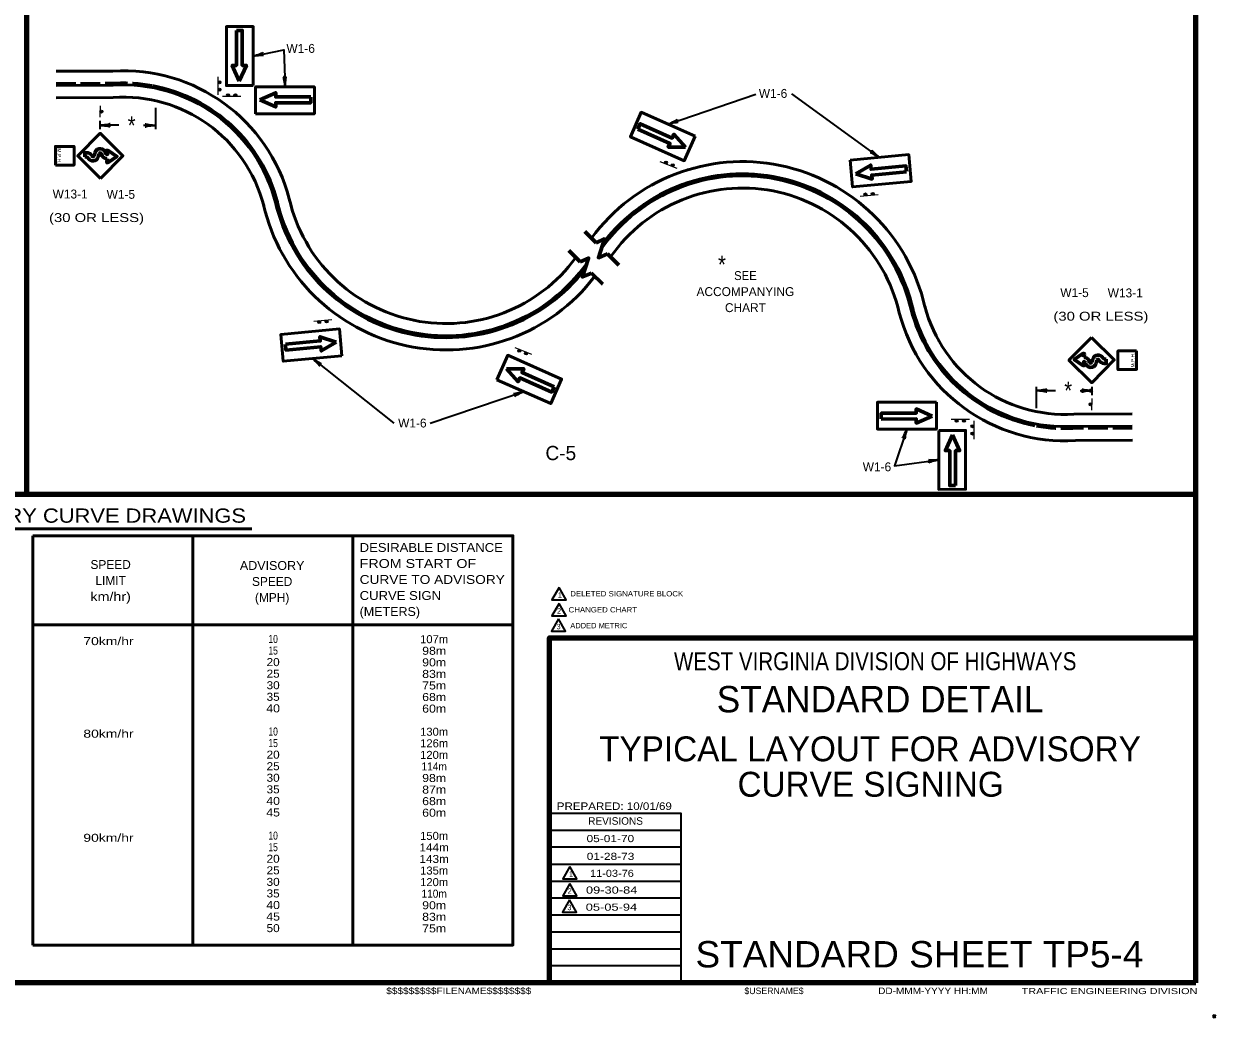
# Model space of a CAD drawing. Extents: x 522 to 1378, y -343 to 201.
# Drawn here: x 975.7 to 1377.6, y -343.4 to -8.5 of the extents above; entities that cross this region are included whole.
import ezdxf
from ezdxf.enums import TextEntityAlignment as Align

# ---------------------------------------------------------------- set-up
doc = ezdxf.new("R2010")
doc.units = 0
doc.header["$LTSCALE"] = 1.1
doc.header["$PDMODE"] = 32
doc.header["$PDSIZE"] = 0.55
doc.linetypes.add('LONG_DASHED', pattern=[7.5, 6, -1.5])
for name, color, linetype, lineweight in [('1', 7, 'Continuous', 53), ('4', 7, 'Continuous', 25), ('61', 7, 'Continuous', 35)]:
    doc.layers.add(name, color=color, linetype=linetype, lineweight=lineweight)

msp = doc.modelspace()

# ---------------------------------------------------------------- hatches: boundary and pattern name
at = {"layer": '4'}
for points in [[(1041.737, -28.71, 1), (1041.739, -27.726, 1)], [(1041.734, -31.178, 1), (1041.737, -30.194, 1)], [(1045.105, -32.546, 1), (1044.121, -32.543, 1)], [(1047.573, -32.548, 1), (1046.589, -32.546, 1)], [(1001.899, -38.586, 1), (1001.907, -37.602, 1)], [(1192.771, -55.429, 1), (1191.86, -55.058, 1)], [(1195.058, -56.357, 1), (1194.147, -55.986, 1)], [(1260.07, -65.984, 1), (1259.089, -66.059, 1)], [(1262.531, -65.79, 1), (1261.55, -65.866, 1)], [(1077.357, -108.892, 1), (1078.338, -108.817, 1)], [(1074.896, -109.086, 1), (1075.877, -109.01, 1)], [(1142.369, -118.519, 1), (1143.28, -118.89, 1)], [(1144.656, -119.447, 1), (1145.567, -119.818, 1)], [(1335.528, -136.29, 1), (1335.52, -137.274, 1)], [(1289.854, -142.328, 1), (1290.838, -142.33, 1)], [(1292.322, -142.33, 1), (1293.306, -142.333, 1)], [(1295.693, -143.698, 1), (1295.69, -144.682, 1)], [(1295.69, -146.166, 1), (1295.688, -147.15, 1)]]:
    msp.add_hatch(color=256, dxfattribs=at).paths.add_polyline_path(points)

# ---------------------------------------------------------------- linework, layer by layer
at = {"layer": '1', "lineweight": 158}
for q in [(1370.988, 194.26), (1370.988, -215.54), (579.388, -331.84)]:
    msp.add_line((1370.988, -331.84), q, dxfattribs=at)
at = {"layer": '1', "lineweight": 13}
msp.add_line((1370.988, -331.84), (1370.988, 194.26), dxfattribs=at)
at = {"layer": '1'}
for p, q in [((986.624, -24.511), (1005.806, -24.42)), ((986.646, -29.295), (1005.829, -29.205)), ((986.666, -33.42), (1005.848, -33.33)), ((1349.591, -139.995), (1329.9, -140.088)), ((1349.611, -144.12), (1330.156, -144.212)), ((1349.633, -148.905), (1330.451, -148.996)), ((894.945, -178.792), (1052.645, -178.792)), ((978.723, -181.085), (978.723, -319.085)), ((1032.723, -181.085), (1032.723, -319.085)), ((1086.723, -181.085), (1086.723, -319.085)), ((978.723, -211.085), (1140.723, -211.085))]:
    msp.add_line(p, q, dxfattribs=at)
at = {"layer": '1', "lineweight": 25}
for p, q in [((1041.238, -32.48), (1041.244, -26.36)), ((1048.875, -33.045), (1042.755, -33.039)), ((1196.078, -57.306), (1190.407, -55.005)), ((1263.868, -66.182), (1257.767, -66.662)), ((1073.559, -108.694), (1079.66, -108.214)), ((1141.349, -117.571), (1147.02, -119.871)), ((1288.552, -141.831), (1294.672, -141.837)), ((1296.189, -142.397), (1296.183, -148.517))]:
    msp.add_line(p, q, dxfattribs=at)
at = {"layer": '1', "linetype": 'LONG_DASHED'}
for p, q in [((986.643, -28.635), (1006.061, -28.543)), ((1349.614, -144.78), (1330.196, -144.872))]:
    msp.add_line(p, q, dxfattribs=at)
at = {"layer": '1', "lineweight": 35}
for p, q in [((1264.294, -53.535), (1234.742, -32.076)), ((1193.058, -42.341), (1222.594, -32.195)), ((1020.118, -36.828), (1020.118, -43.957)), ((1001.408, -41.21), (1001.408, -43.957)), ((1007.763, -42.716), (1001.408, -42.695)), ((1020.118, -42.757), (1016.078, -42.744)), ((1073.133, -121.341), (1100.484, -143.092)), ((1144.37, -132.535), (1112.83, -143.21)), ((1317.31, -138.048), (1317.31, -130.919)), ((1317.31, -132.119), (1323.664, -132.14)), ((1331.979, -132.168), (1336.019, -132.181)), ((1336.019, -133.666), (1336.019, -130.919)), ((1197.488, -280.44), (1152.988, -280.44)), ((1197.488, -286.14), (1152.988, -286.14)), ((1197.488, -291.94), (1152.988, -291.94)), ((1197.488, -297.64), (1152.988, -297.64)), ((1197.488, -303.34), (1152.988, -303.34)), ((1197.488, -309.04), (1152.988, -309.04)), ((1197.488, -314.74), (1152.988, -314.74)), ((1197.488, -320.44), (1152.988, -320.44)), ((1197.488, -326.14), (1152.988, -326.14))]:
    msp.add_line(p, q, dxfattribs=at)
at = {"layer": '1', "lineweight": 60}
for p, q in [((999.435, -52.996), (999.754, -51.917)), ((997.007, -53.385), (996.318, -53.385)), ((1001.143, -52.326), (1000.833, -53.415)), ((1003.68, -54.904), (1003.97, -53.945)), ((1164.953, -78.53), (1168.774, -82.303)), ((1159.557, -84.975), (1163.378, -88.747)), ((1172.613, -86.093), (1176.435, -89.865)), ((1167.218, -92.538), (1171.039, -96.31)), ((1333.443, -120.001), (1333.153, -120.96)), ((1335.98, -122.579), (1336.29, -121.49)), ((1337.688, -121.909), (1337.368, -122.988)), ((1340.115, -121.52), (1340.805, -121.52))]:
    msp.add_line(p, q, dxfattribs=at)
at = {"layer": '1'}
for points in [[(1053.122, -29.291), (1053.102, -9.425), (1044.048, -9.434), (1044.067, -29.3)], [(1053.907, -38.821), (1073.773, -38.801), (1073.764, -29.746), (1053.898, -29.766)], [(1202.138, -46.368), (1183.977, -38.314), (1180.306, -46.591), (1198.467, -54.645)], [(1001.574, -60.641), (993.904, -53.038), (1001.507, -45.368), (1009.177, -52.971)], [(986.395, -56.141), (986.368, -49.841), (992.668, -49.813), (992.695, -56.113)], [(1254.406, -54.483), (1274.182, -52.587), (1275.046, -61.601), (1255.271, -63.497)], [(1083.021, -120.393), (1063.245, -122.289), (1062.381, -113.275), (1082.157, -111.379)], [(1335.853, -114.235), (1343.523, -121.838), (1335.92, -129.508), (1328.25, -121.905)], [(1135.289, -128.508), (1153.449, -136.562), (1157.121, -128.285), (1138.96, -120.231)], [(1351.032, -118.735), (1351.059, -125.035), (1344.759, -125.063), (1344.732, -118.763)], [(1283.52, -136.055), (1263.654, -136.075), (1263.663, -145.13), (1283.529, -145.11)], [(1284.305, -145.586), (1284.325, -165.452), (1293.38, -165.442), (1293.36, -145.577)]]:
    msp.add_lwpolyline(points, close=True, dxfattribs=at)
at = {"layer": '1', "lineweight": 60}
for points in [[(1048.413, -27.829), (1046.056, -22.503), (1047.447, -22.502), (1047.436, -10.694)], [(1047.484, -10.694), (1049.404, -10.692), (1049.416, -22.5), (1050.831, -22.499), (1048.413, -27.829)], [(1055.369, -34.112), (1060.694, -31.754), (1060.696, -33.146), (1072.504, -33.135)], [(1072.504, -33.183), (1072.505, -35.102), (1060.697, -35.114), (1060.699, -36.53), (1055.369, -34.112)], [(1198.889, -50.077), (1193.065, -50.067), (1193.629, -48.794), (1182.835, -44.007)], [(1182.855, -43.963), (1183.633, -42.208), (1194.427, -46.995), (1195.001, -45.701), (1198.889, -50.077)], [(996.318, -53.385), (996.318, -51.937), (997.009, -51.937)], [(1003.73, -52.496), (1003.97, -52.496), (1003.68, -51.537)], [(1004.159, -51.178), (1007.116, -53.225), (1004.159, -55.273)], [(1273.46, -58.302), (1273.277, -56.391), (1261.522, -57.518), (1261.387, -56.108), (1256.315, -59.03)], [(1256.315, -59.03), (1261.843, -60.862), (1261.71, -59.477), (1273.465, -58.35)], [(1168.774, -82.303), (1171.642, -81.037), (1169.56, -87.356), (1172.613, -86.093)], [(1163.378, -88.747), (1166.246, -87.482), (1164.165, -93.801), (1167.218, -92.538)], [(1081.112, -115.846), (1075.584, -114.014), (1075.717, -115.399), (1063.962, -116.526)], [(1063.967, -116.574), (1064.15, -118.485), (1075.905, -117.358), (1076.04, -118.768), (1081.112, -115.846)], [(1332.963, -123.727), (1330.006, -121.68), (1332.963, -119.632)], [(1333.393, -122.409), (1333.153, -122.409), (1333.443, -123.368)], [(1340.805, -121.52), (1340.805, -122.968), (1340.114, -122.968)], [(1138.538, -124.799), (1144.362, -124.809), (1143.798, -126.082), (1154.592, -130.869)], [(1154.572, -130.913), (1153.794, -132.668), (1143, -127.881), (1142.426, -129.175), (1138.538, -124.799)], [(1264.924, -141.694), (1264.922, -139.774), (1276.73, -139.762), (1276.728, -138.346), (1282.059, -140.764)], [(1282.059, -140.764), (1276.733, -143.122), (1276.731, -141.73), (1264.923, -141.742)], [(1289.943, -164.182), (1288.023, -164.184), (1288.012, -152.376), (1286.596, -152.377), (1289.014, -147.047)], [(1289.014, -147.047), (1291.371, -152.373), (1289.98, -152.374), (1289.991, -164.182)]]:
    msp.add_lwpolyline(points, dxfattribs=at)
at = {"layer": '1', "lineweight": 35}
for points in [[(1053.112, -19.358), (1063.428, -17.232), (1063.831, -29.756)], [(1273.596, -145.12), (1269.432, -157.519), (1284.315, -155.519)], [(1197.488, -331.84), (1197.488, -274.74), (1152.988, -274.74)]]:
    msp.add_lwpolyline(points, dxfattribs=at)
at = {"layer": '1'}
msp.add_lwpolyline([(978.723, -181.085), (1140.723, -181.085), (1140.723, -319.085), (978.723, -319.085)], dxfattribs=at)
at = {"layer": '1', "lineweight": 35}
for points in [[(1156.246, -198.582), (1153.846, -202.739), (1158.646, -202.739)], [(1156.246, -203.988), (1153.846, -208.145), (1158.646, -208.145)], [(1156.076, -209.158), (1153.676, -213.315), (1158.476, -213.315)], [(1159.88, -292.58), (1157.48, -296.737), (1162.28, -296.737)], [(1159.881, -298.34), (1157.481, -302.497), (1162.281, -302.497)], [(1159.796, -303.853), (1157.396, -308.01), (1162.196, -308.01)]]:
    msp.add_lwpolyline(points, close=True, dxfattribs=at)
at = {"layer": '1', "lineweight": 158}
msp.add_lwpolyline([(1152.988, -331.84), (1152.988, -215.54), (1370.988, -215.54)], dxfattribs=at)
at = {"layer": '1'}
for centre, radius, start, end in [((1009.373, -82.046), 57.736, 14.56862, 93.54201), ((1009.373, -82.046), 52.951, 14.56862, 93.83748), ((1009.373, -82.046), 53.611, 14.56862, 79.46575), ((1009.373, -82.046), 48.826, 14.56862, 94.13854), ((1218.138, -118.129), 63.174, 13.03125, 143.72905), ((1218.138, -118.129), 58.389, 13.03125, 144.53374), ((1218.138, -118.129), 59.049, 13.03125, 142.57673), ((1218.138, -118.129), 54.264, 13.03125, 145.11432), ((1118.119, -55.287), 54.264, 193.03125, 323.83059), ((1118.119, -55.287), 63.174, 193.03125, 322.63009), ((1118.119, -55.287), 59.049, 193.03125, 322.62534), ((1118.119, -55.287), 58.389, 193.03125, 324.5883), ((1326.884, -91.37), 48.826, 194.56862, 273.54201), ((1326.884, -91.37), 57.736, 194.56862, 273.54201), ((1326.884, -91.37), 53.611, 194.56862, 259.04913), ((1326.884, -91.37), 52.951, 194.56862, 273.54201)]:
    msp.add_arc(centre, radius, start, end, dxfattribs=at)
at = {"layer": '1', "linetype": 'LONG_DASHED'}
for centre, start, end in [((1009.373, -82.045), 79.71209, 93.54201), ((1326.884, -91.37), 259.71209, 273.54201)]:
    msp.add_arc(centre, 53.611, start, end, dxfattribs=at)
at = {"layer": '1', "lineweight": 60}
for centre, radius, start, end in [((997.009, -53.778), 1.842, 23.49845, 90.00151), ((1001.521, -52.429), 1.845, 8.4015, 163.7693), ((1001.52, -52.438), 0.393, 8.0932, 163.55726), ((1003.732, -52.106), 0.389, 187.89539, 270.08644), ((1003.989, -51.446), 0.32, 58.09657, 196.71414), ((997, -53.786), 0.396, 22.25639, 88.72657), ((999.058, -52.897), 1.845, 203.60293, 343.79173), ((999.056, -52.887), 0.391, 203.48693, 343.50236), ((1003.731, -52.106), 1.843, 188.64396, 270.21119), ((1003.989, -54.998), 0.32, 163.28586, 301.90343), ((1333.134, -119.907), 0.32, 343.28586, 121.90343), ((1338.065, -122.008), 1.845, 23.60293, 163.79173), ((1333.134, -123.459), 0.32, 238.09657, 16.71414), ((1333.391, -122.799), 1.843, 8.64396, 90.21119), ((1333.391, -122.799), 0.389, 7.89539, 90.08644), ((1335.601, -122.476), 1.845, 188.4015, 343.7693), ((1335.603, -122.466), 0.393, 188.0932, 343.55726), ((1338.066, -122.017), 0.391, 23.48693, 163.50236), ((1340.114, -121.127), 1.842, 203.49845, 270.00151), ((1340.123, -121.119), 0.396, 202.25639, 268.72657)]:
    msp.add_arc(centre, radius, start, end, dxfattribs=at)
at = {"layer": '1', "lineweight": 40}
for centre, major_axis, ratio, start_param, end_param in [((1054.328, -18.768), (-2.061, -0.616), 0.122415, 0.8963533, 3.1415927), ((1054.328, -18.768), (-2.061, -0.616), 0.122415, 0.8963533, 3.1415927), ((1054.48, -19.335), (-2.107, -0.219), 0.07063, 3.1407148, 5.41811), ((1054.48, -19.335), (-2.107, -0.219), 0.07063, 3.1407148, 5.41811), ((1063.458, -28.458), (0.256, -2.136), 0.122415, 0.8963533, 3.1415927), ((1064.042, -28.404), (-0.143, -2.113), 0.07063, 3.1407148, 5.41811), ((1002.752, -42.953), (-2.107, 0.218), 0.07063, 3.1407148, 5.41811), ((1002.752, -42.953), (-2.107, 0.218), 0.07063, 3.1407148, 5.41811), ((1002.719, -42.368), (-2.143, -0.18), 0.122415, 0.8963533, 3.1415927), ((1002.719, -42.368), (-2.143, -0.18), 0.122415, 0.8963533, 3.1415927), ((1018.807, -43.084), (2.143, 0.18), 0.122415, 0.8963533, 3.1415927), ((1018.807, -43.084), (2.143, 0.18), 0.122415, 0.8963533, 3.1415927), ((1018.774, -42.499), (2.107, -0.218), 0.07063, 3.1407148, 5.41811), ((1018.774, -42.499), (2.107, -0.218), 0.07063, 3.1407148, 5.41811), ((1194.188, -41.602), (-1.966, -0.873), 0.122415, 0.8963533, 3.1415927), ((1194.188, -41.602), (-1.966, -0.873), 0.122415, 0.8963533, 3.1415927), ((1194.412, -42.144), (-2.062, -0.485), 0.07063, 3.1407148, 5.41811), ((1194.412, -42.144), (-2.062, -0.485), 0.07063, 3.1407148, 5.41811), ((1263.04, -53.034), (1.844, -1.107), 0.122415, 0.8963533, 3.1415927), ((1263.355, -52.54), (1.582, -1.409), 0.07063, 3.1407148, 5.41811), ((1074.027, -122.377), (-1.518, 1.477), 0.07063, 3.1407148, 5.41811), ((1074.027, -122.377), (-1.518, 1.477), 0.07063, 3.1407148, 5.41811), ((1074.364, -121.896), (-1.794, 1.187), 0.122415, 0.8963533, 3.1415927), ((1074.364, -121.896), (-1.794, 1.187), 0.122415, 0.8963533, 3.1415927), ((1143.014, -132.726), (2.064, 0.476), 0.07063, 3.1407148, 5.41811), ((1143.235, -133.269), (1.97, 0.864), 0.122415, 0.8963533, 3.1415927), ((1318.653, -132.378), (-2.107, 0.218), 0.07063, 3.1407148, 5.41811), ((1318.653, -132.378), (-2.107, 0.218), 0.07063, 3.1407148, 5.41811), ((1318.62, -131.792), (-2.143, -0.18), 0.122415, 0.8963533, 3.1415927), ((1318.62, -131.792), (-2.143, -0.18), 0.122415, 0.8963533, 3.1415927), ((1334.708, -132.509), (2.143, 0.18), 0.122415, 0.8963533, 3.1415927), ((1334.708, -132.509), (2.143, 0.18), 0.122415, 0.8963533, 3.1415927), ((1334.675, -131.923), (2.107, -0.218), 0.07063, 3.1407148, 5.41811), ((1334.675, -131.923), (2.107, -0.218), 0.07063, 3.1407148, 5.41811), ((1272.927, -146.314), (0.871, 1.931), 0.07063, 3.1407148, 5.41811), ((1272.927, -146.314), (0.871, 1.931), 0.07063, 3.1407148, 5.41811), ((1273.493, -146.467), (0.505, 2.091), 0.122415, 0.8963533, 3.1415927), ((1273.493, -146.467), (0.505, 2.091), 0.122415, 0.8963533, 3.1415927), ((1282.948, -155.446), (2.117, 0.072), 0.07063, 3.1407148, 5.41811), ((1283.061, -156.022), (2.099, 0.471), 0.122415, 0.8963533, 3.1415927)]:
    msp.add_ellipse(centre, major_axis=major_axis, ratio=ratio, start_param=start_param, end_param=end_param, dxfattribs=at)
at = {"layer": '1'}
for p in [(1335.663, -132.18), (1377.288, -343.14)]:
    msp.add_point(p, dxfattribs=at)
at = {"layer": '4'}
for p, q in [((1001.439, -36.17), (1001.408, -40.01)), ((1335.988, -138.706), (1336.019, -134.866))]:
    msp.add_line(p, q, dxfattribs=at)
for centre in [(1041.738, -28.218), (1041.736, -30.686), (1044.613, -32.545), (1047.081, -32.547), (1001.903, -38.094), (1192.315, -55.244), (1194.602, -56.171), (1259.58, -66.022), (1262.04, -65.828), (1077.847, -108.855), (1075.387, -109.048), (1142.825, -118.705), (1145.112, -119.632), (1335.524, -136.782), (1290.346, -142.329), (1292.814, -142.331), (1295.691, -144.19), (1295.689, -146.658)]:
    msp.add_circle(centre, 0.492, dxfattribs=at)
at = {"layer": '61', "lineweight": 158}
for p, q in [((976.669, 194.21), (976.686, -167.206)), ((1370.988, -167.219), (579.357, -167.194))]:
    msp.add_line(p, q, dxfattribs=at)
at = {"layer": '61', "lineweight": 53}
for q in [(1218.288, -331.84), (1218.288, -331.84), (1218.288, -331.84), (1218.588, -331.84), (1218.588, -331.84)]:
    msp.add_line((1370.988, -331.84), q, dxfattribs=at)

# ---------------------------------------------------------------- texts
at = {"layer": '1'}
for s, height, p in [('W1-6', 3, (1069.105, -18.282)), ('W1-6', 3, (1228.435, -33.457)), ('W13-1', 3, (991.353, -67.382)), ('W1-5', 3, (1008.46, -67.482)), ('ACCOMPANYING', 3, (1219.122, -100.287)), ('W1-5', 3, (1330.12, -100.629)), ('W13-1', 3, (1347.228, -100.728)), ('CHART', 3, (1219.122, -105.687)), ('W1-6', 3, (1106.774, -144.596)), ('C-5', 4.8, (1156.848, -155.606)), ('W1-6', 3, (1263.486, -159.357)), ('SPEED', 3, (1005.013, -192.303)), ('LIMIT', 3, (1005.013, -197.703)), ('SPEED', 3, (1059.492, -198.027)), ('(MPH)', 3, (1059.492, -203.427)), ('1', 1.8, (1156.564, -201.981)), ('STANDARD DETAIL', 8.881, (1264.538, -240.64)), ('TYPICAL LAYOUT FOR ADVISORY', 8.391, (1261.149, -257.141)), ('CURVE SIGNING', 8.391, (1261.354, -269.077)), ('1', 1.8, (1160.297, -296.016))]:
    msp.add_text(s, height=height, dxfattribs=at).set_placement(p, align=Align.CENTER)
at = {"layer": '1', "width": 0.85}
for p in [(1010.753, -45.726), (1326.654, -135.15)]:
    msp.add_text('*', height=6, rotation=359.81, dxfattribs=at).set_placement(p)
at = {"layer": '1'}
for rotation, p in [(270.062, (987.063, -50.499)), (90.062, (1350.364, -124.377))]:
    msp.add_text('M.P.H.', height=1.2, rotation=rotation, dxfattribs=at).set_placement(p)
for s, height, width, p in [('(30 OR LESS)', 3, 1.25, (1000.251, -75.329)), ('SEE', 3, 0.95, (1219.122, -94.887)), ('(30 OR LESS)', 3, 1.25, (1339.019, -108.575)), ('CHART FOR ADVISORY CURVE DRAWINGS', 4.8, 1.15, (973.772, -176.704)), ('ADVISORY', 3, 1.05, (1059.492, -192.627)), ('km/hr)', 3, 1.2, (1005.013, -203.103)), ('DELETED SIGNATURE BLOCK', 1.8, 1.1, (1179.087, -201.549)), ('2', 1.8, 0.9, (1156.246, -207.387)), ('CHANGED CHART', 1.8, 1.1, (1171.017, -206.954)), ('3', 1.8, 0.9, (1156.083, -212.642)), ('ADDED METRIC', 1.8, 1.05, (1169.668, -212.294)), ('70km/hr', 2.7, 1.3, (1004.282, -217.984)), ('10', 2.7, 0.8, (1059.817, -217.249)), ('107m', 2.7, 1.05, (1114.132, -217.328)), ('15', 2.7, 0.8, (1059.817, -221.149)), ('98m', 2.7, 1.15, (1114.132, -221.228)), ('WEST VIRGINIA DIVISION OF HIGHWAYS', 6.089, 0.85, (1262.888, -226.44)), ('20', 2.7, 1.1, (1059.817, -225.049)), ('90m', 2.7, 1.15, (1114.132, -225.128)), ('25', 2.7, 1.1, (1059.817, -228.949)), ('83m', 2.7, 1.15, (1114.132, -229.028)), ('30', 2.7, 1.1, (1059.817, -232.849)), ('75m', 2.7, 1.15, (1114.132, -232.928)), ('35', 2.7, 1.1, (1059.817, -236.749)), ('68m', 2.7, 1.15, (1114.132, -236.828)), ('40', 2.7, 1.15, (1059.817, -240.649)), ('60m', 2.7, 1.15, (1114.132, -240.728)), ('80km/hr', 2.7, 1.3, (1004.282, -249.184)), ('10', 2.7, 0.8, (1059.817, -248.449)), ('130m', 2.7, 1.05, (1114.132, -248.528)), ('15', 2.7, 0.8, (1059.817, -252.349)), ('126m', 2.7, 1.05, (1114.132, -252.428)), ('20', 2.7, 1.1, (1059.817, -256.249)), ('120m', 2.7, 1.05, (1114.132, -256.328)), ('25', 2.7, 1.1, (1059.817, -260.149)), ('114m', 2.7, 0.95, (1114.132, -260.228)), ('30', 2.7, 1.1, (1059.817, -264.048)), ('98m', 2.7, 1.15, (1114.132, -264.128)), ('40', 2.7, 1.15, (1059.817, -271.849)), ('35', 2.7, 1.1, (1059.817, -267.949)), ('87m', 2.7, 1.15, (1114.132, -268.028)), ('68m', 2.7, 1.15, (1114.132, -271.928)), ('45', 2.7, 1.15, (1059.817, -275.749)), ('60m', 2.7, 1.15, (1114.132, -275.828)), ('10', 2.7, 0.8, (1059.817, -283.548)), ('150m', 2.7, 1.05, (1114.132, -283.628)), ('90km/hr', 2.7, 1.3, (1004.282, -284.284)), ('15', 2.7, 0.8, (1059.817, -287.449)), ('144m', 2.7, 1.1, (1114.132, -287.528)), ('05-01-70', 2.4, 1.25, (1173.565, -284.403)), ('20', 2.7, 1.1, (1059.817, -291.349)), ('143m', 2.7, 1.1, (1114.132, -291.428)), ('01-28-73', 2.4, 1.25, (1173.63, -290.394)), ('25', 2.7, 1.1, (1059.817, -295.249)), ('135m', 2.7, 1.05, (1114.132, -295.328)), ('30', 2.7, 1.1, (1059.817, -299.149)), ('120m', 2.7, 1.05, (1114.132, -299.228)), ('11-03-76', 2.4, 1.15, (1174.098, -296.117)), ('35', 2.7, 1.1, (1059.817, -303.048)), ('110m', 2.7, 0.95, (1114.132, -303.128)), ('2', 1.8, 0.9, (1159.836, -301.821)), ('09-30-84', 2.4, 1.35, (1174.009, -301.753)), ('40', 2.7, 1.15, (1059.817, -306.949)), ('90m', 2.7, 1.15, (1114.132, -307.028)), ('05-05-94', 2.4, 1.35, (1173.934, -307.52)), ('45', 2.7, 1.15, (1059.817, -310.849)), ('83m', 2.7, 1.15, (1114.132, -310.928)), ('3', 1.8, 0.9, (1159.758, -307.334)), ('50', 2.7, 1.1, (1059.817, -314.749)), ('75m', 2.7, 1.15, (1114.132, -314.828))]:
    msp.add_text(s, height=height, dxfattribs=dict(at, width=width)).set_placement(p, align=Align.CENTER)
for s, height, width, p in [('*', 6, 0.85, (1209.88, -92.654)), ('DESIRABLE DISTANCE', 3, 1.1, (1089.002, -186.552)), ('FROM START OF', 3, 1.2, (1089.002, -191.952)), ('CURVE TO ADVISORY', 3, 1.15, (1089.002, -197.352)), ('CURVE SIGN', 3, 1.1, (1089.002, -202.752)), ('(METERS)', 3, 1.05, (1089.002, -208.151)), ('PREPARED: 10/01/69', 2.537, 1.15, (1155.488, -273.54)), ('STANDARD SHEET TP5-4 ', 8.881, 1.05, (1202.288, -326.64)), ('$$$$$$$$$FILENAME$$$$$$$$', 2.2, 1.15, (1097.988, -335.64)), ('DD-MMM-YYYY HH:MM', 2.2, 1.15, (1263.888, -335.64)), ('TRAFFIC ENGINEERING DIVISION', 2.031, 1.35, (1312.288, -335.64))]:
    msp.add_text(s, height=height, dxfattribs=dict(at, width=width)).set_placement(p)
for s, height, p in [('REVISIONS', 2.537, (1166.088, -278.54)), ('$USERNAME$', 2.2, (1218.788, -335.64))]:
    msp.add_text(s, height=height, dxfattribs=at).set_placement(p)

doc.saveas('drawing.dxf')
